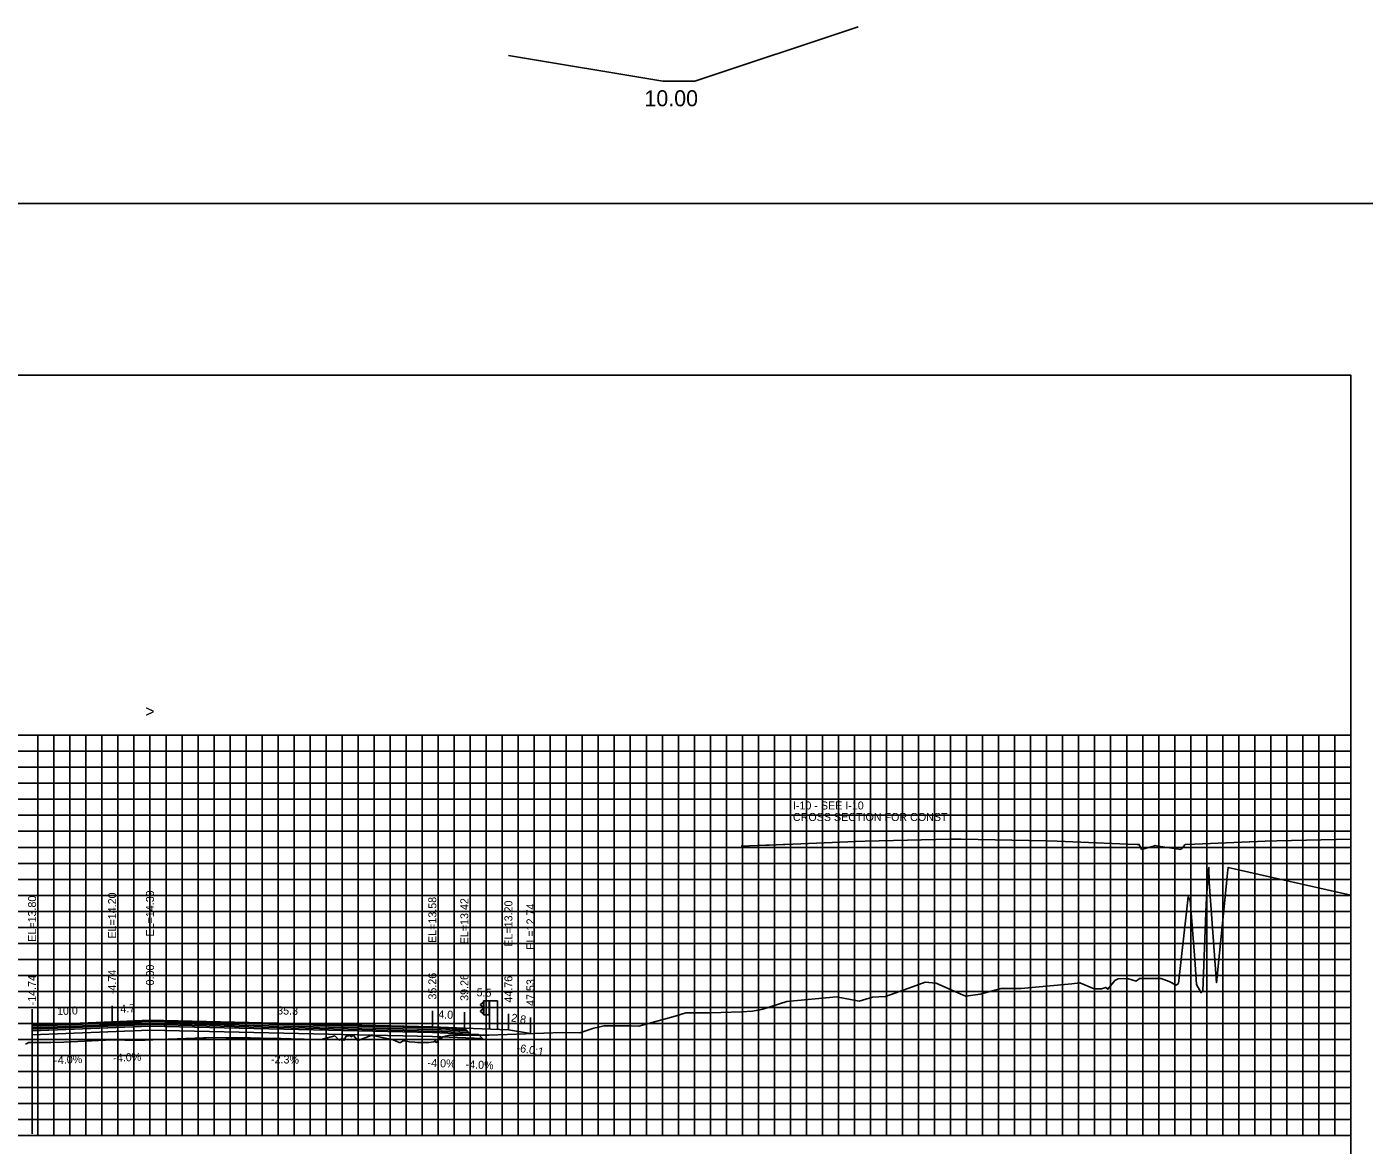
# Model space of a CAD drawing. Extents: x 1797518 to 1804843, y 248068 to 251132.
# Drawn here: x 1804315.6 to 1804482.7, y 250173.2 to 250312.9 of the extents above; entities that cross this region are included whole.
import ezdxf

# ---------------------------------------------------------------- set-up
doc = ezdxf.new("R2010")
doc.units = 0
for name, color, linetype in [('1', 7, 'Continuous'), ('3', 7, 'Continuous'), ('4', 7, 'Continuous'), ('60', 7, 'Continuous'), ('BASE', 7, 'Continuous'), ('CL-CNST', 7, 'Continuous'), ('Level 1', 7, 'Continuous'), ('Level 62', 7, 'Continuous'), ('LOWER BINDER', 7, 'Continuous'), ('M-ROADS', 7, 'Continuous'), ('UPPER BINDER', 7, 'Continuous'), ('WEARING', 7, 'Continuous')]:
    doc.layers.add(name, color=color, linetype=linetype)

msp = doc.modelspace()

# ---------------------------------------------------------------- linework, layer by layer
for p, q in [((1804326.27, 250188.63), (1804326.27, 250190.63)), ((1804331, 250188.82), (1804331, 250190.82)), ((1804316.27, 250188.23), (1804316.27, 250190.23)), ((1804366.27, 250188.01), (1804366.27, 250190.01)), ((1804370.27, 250187.85), (1804370.27, 250189.85)), ((1804375.77, 250187.63), (1804375.77, 250189.63)), ((1804378.53, 250187.17), (1804378.53, 250189.17))]:
    msp.add_line(p, q)
msp.add_lwpolyline([(1804181, 250079.43), (1804481, 250079.43), (1804481, 250269.43), (1804181, 250269.43)], close=True)
at = {"layer": '1'}
for p, q in [((1804419.48, 250312.95), (1804399.05, 250306.14)), ((1804375.77, 250309.35), (1804395.05, 250306.14)), ((1804399.05, 250306.14), (1804395.05, 250306.14))]:
    msp.add_line(p, q, dxfattribs=at)
msp.add_lwpolyline([(1804164.33, 250290.86), (1804501.93, 250290.86), (1804501.93, 250044.24), (1804164.33, 250044.24)], close=True, dxfattribs=at)
at = {"layer": '3'}
msp.add_line((1804316.27, 250188.41), (1804316.27, 250174.63), dxfattribs=at)
at = {"layer": '60'}
for p, q in [((1804481, 250174.43), (1804481, 250224.43)), ((1804481.06, 250224.43), (1804481, 250224.43)), ((1804481.06, 250214.43), (1804481, 250214.43)), ((1804481.06, 250204.43), (1804481, 250204.43)), ((1804481.06, 250194.43), (1804481, 250194.43)), ((1804481.06, 250184.43), (1804481, 250184.43)), ((1804181, 250174.43), (1804481, 250174.43)), ((1804321, 250174.37), (1804321, 250174.43)), ((1804331, 250174.37), (1804331, 250174.43)), ((1804341, 250174.37), (1804341, 250174.43)), ((1804351, 250174.37), (1804351, 250174.43)), ((1804361, 250174.37), (1804361, 250174.43)), ((1804371, 250174.37), (1804371, 250174.43)), ((1804381, 250174.37), (1804381, 250174.43)), ((1804391, 250174.37), (1804391, 250174.43)), ((1804401, 250174.37), (1804401, 250174.43)), ((1804411, 250174.37), (1804411, 250174.43)), ((1804421, 250174.37), (1804421, 250174.43)), ((1804431, 250174.37), (1804431, 250174.43)), ((1804441, 250174.37), (1804441, 250174.43)), ((1804451, 250174.37), (1804451, 250174.43)), ((1804461, 250174.37), (1804461, 250174.43)), ((1804471, 250174.37), (1804471, 250174.43)), ((1804481, 250174.37), (1804481, 250174.43)), ((1804481.06, 250174.43), (1804481, 250174.43))]:
    msp.add_line(p, q, dxfattribs=at)
at = {"layer": 'BASE'}
msp.add_lwpolyline([(1804316.27, 250187.51), (1804331, 250188.1), (1804366.27, 250187.29), (1804371.02, 250187.1), (1804372.02, 250187.06), (1804372.54, 250186.54), (1804366.27, 250186.79), (1804331, 250187.6), (1804316.27, 250187.01)], close=True, dxfattribs=at)
at = {"layer": 'CL-CNST'}
for points in [[(1804404.83, 250210.58), (1804407.91, 250210.7), (1804408.33, 250210.72), (1804410.09, 250210.79), (1804410.33, 250210.8), (1804419.13, 250211.15), (1804420.33, 250211.2), (1804430.9, 250211.43), (1804432.33, 250211.46), (1804442.9, 250211.23), (1804444.33, 250211.2), (1804453.14, 250210.84), (1804454.33, 250210.8), (1804454.55, 250210.79), (1804454.58, 250210.79), (1804454.83, 250210.26), (1804454.87, 250210.18), (1804456.37, 250210.59), (1804456.58, 250210.65), (1804456.92, 250210.59), (1804459.78, 250210.18), (1804459.84, 250210.26), (1804460.32, 250210.8), (1804461.51, 250210.84), (1804470.32, 250211.2), (1804471.74, 250211.23), (1804481, 250211.43)], [(1804316.27, 250188.23), (1804326.27, 250188.63), (1804331, 250188.82), (1804366.27, 250188.01), (1804370.27, 250187.85), (1804375.77, 250187.63), (1804378.53, 250187.17)]]:
    msp.add_lwpolyline(points, dxfattribs=at)
at = {"layer": 'Level 1'}
for p, q in [((1804372.65, 250191.1), (1804372.28, 250190.8)), ((1804372.28, 250190.73), (1804372.65, 250190.45)), ((1804372.65, 250190.31), (1804372.28, 250190.01)), ((1804372.65, 250191.25), (1804372.65, 250189.5)), ((1804374.4, 250191.25), (1804372.65, 250191.25)), ((1804372.7, 250191.25), (1804372.7, 250189.5)), ((1804373.35, 250191.25), (1804373.35, 250189.5)), ((1804373.4, 250191.25), (1804373.4, 250187.73)), ((1804374.4, 250191.25), (1804374.4, 250187.69)), ((1804372.28, 250189.94), (1804372.65, 250189.65)), ((1804373.4, 250189.5), (1804372.65, 250189.5))]:
    msp.add_line(p, q, dxfattribs=at)
for centre in [(1804372.32, 250190.77), (1804372.32, 250189.97)]:
    msp.add_arc(centre, 0.05, 135, 226.6208, dxfattribs=at)
at = {"layer": 'Level 62'}
for p, q in [((1804181, 250224.43), (1804481, 250224.43)), ((1804317, 250174.43), (1804317, 250224.43)), ((1804319, 250174.43), (1804319, 250224.43)), ((1804321, 250174.43), (1804321, 250224.43)), ((1804323, 250174.43), (1804323, 250224.43)), ((1804325, 250174.43), (1804325, 250224.43)), ((1804327, 250174.43), (1804327, 250224.43)), ((1804329, 250174.43), (1804329, 250224.43)), ((1804331, 250174.43), (1804331, 250224.43)), ((1804333, 250174.43), (1804333, 250224.43)), ((1804335, 250174.43), (1804335, 250224.43)), ((1804337, 250174.43), (1804337, 250224.43)), ((1804339, 250174.43), (1804339, 250224.43)), ((1804341, 250174.43), (1804341, 250224.43)), ((1804343, 250174.43), (1804343, 250224.43)), ((1804345, 250174.43), (1804345, 250224.43)), ((1804347, 250174.43), (1804347, 250224.43)), ((1804349, 250174.43), (1804349, 250224.43)), ((1804351, 250174.43), (1804351, 250224.43)), ((1804353, 250174.43), (1804353, 250224.43)), ((1804355, 250174.43), (1804355, 250224.43)), ((1804357, 250174.43), (1804357, 250224.43)), ((1804359, 250174.43), (1804359, 250224.43)), ((1804361, 250174.43), (1804361, 250224.43)), ((1804363, 250174.43), (1804363, 250224.43)), ((1804365, 250174.43), (1804365, 250224.43)), ((1804367, 250174.43), (1804367, 250224.43)), ((1804369, 250174.43), (1804369, 250224.43)), ((1804371, 250174.43), (1804371, 250224.43)), ((1804373, 250174.43), (1804373, 250224.43)), ((1804375, 250174.43), (1804375, 250224.43)), ((1804377, 250174.43), (1804377, 250224.43)), ((1804379, 250174.43), (1804379, 250224.43)), ((1804381, 250174.43), (1804381, 250224.43)), ((1804383, 250174.43), (1804383, 250224.43)), ((1804385, 250174.43), (1804385, 250224.43)), ((1804387, 250174.43), (1804387, 250224.43)), ((1804389, 250174.43), (1804389, 250224.43)), ((1804391, 250174.43), (1804391, 250224.43)), ((1804393, 250174.43), (1804393, 250224.43)), ((1804395, 250174.43), (1804395, 250224.43)), ((1804397, 250174.43), (1804397, 250224.43)), ((1804399, 250174.43), (1804399, 250224.43)), ((1804401, 250174.43), (1804401, 250224.43)), ((1804403, 250174.43), (1804403, 250224.43)), ((1804405, 250174.43), (1804405, 250224.43)), ((1804407, 250174.43), (1804407, 250224.43)), ((1804409, 250174.43), (1804409, 250224.43)), ((1804411, 250174.43), (1804411, 250224.43)), ((1804413, 250174.43), (1804413, 250224.43)), ((1804415, 250174.43), (1804415, 250224.43)), ((1804417, 250174.43), (1804417, 250224.43)), ((1804419, 250174.43), (1804419, 250224.43)), ((1804421, 250174.43), (1804421, 250224.43)), ((1804423, 250174.43), (1804423, 250224.43)), ((1804425, 250174.43), (1804425, 250224.43)), ((1804427, 250174.43), (1804427, 250224.43)), ((1804429, 250174.43), (1804429, 250224.43)), ((1804431, 250174.43), (1804431, 250224.43)), ((1804433, 250174.43), (1804433, 250224.43)), ((1804435, 250174.43), (1804435, 250224.43)), ((1804437, 250174.43), (1804437, 250224.43)), ((1804439, 250174.43), (1804439, 250224.43)), ((1804441, 250174.43), (1804441, 250224.43)), ((1804443, 250174.43), (1804443, 250224.43)), ((1804445, 250174.43), (1804445, 250224.43)), ((1804447, 250174.43), (1804447, 250224.43)), ((1804449, 250174.43), (1804449, 250224.43)), ((1804451, 250174.43), (1804451, 250224.43)), ((1804453, 250174.43), (1804453, 250224.43)), ((1804455, 250174.43), (1804455, 250224.43)), ((1804457, 250174.43), (1804457, 250224.43)), ((1804459, 250174.43), (1804459, 250224.43)), ((1804461, 250174.43), (1804461, 250224.43)), ((1804463, 250174.43), (1804463, 250224.43)), ((1804465, 250174.43), (1804465, 250224.43)), ((1804467, 250174.43), (1804467, 250224.43)), ((1804469, 250174.43), (1804469, 250224.43)), ((1804471, 250174.43), (1804471, 250224.43)), ((1804473, 250174.43), (1804473, 250224.43)), ((1804475, 250174.43), (1804475, 250224.43)), ((1804477, 250174.43), (1804477, 250224.43)), ((1804479, 250174.43), (1804479, 250224.43)), ((1804481, 250174.43), (1804481, 250224.43)), ((1804181, 250222.43), (1804481, 250222.43)), ((1804181, 250220.43), (1804481, 250220.43)), ((1804181, 250218.43), (1804481, 250218.43)), ((1804181, 250216.43), (1804481, 250216.43)), ((1804181, 250214.43), (1804481, 250214.43)), ((1804181, 250212.43), (1804481, 250212.43)), ((1804181, 250210.43), (1804481, 250210.43)), ((1804181, 250208.43), (1804481, 250208.43)), ((1804181, 250206.43), (1804481, 250206.43)), ((1804181, 250204.43), (1804481, 250204.43)), ((1804181, 250202.43), (1804481, 250202.43)), ((1804181, 250200.43), (1804481, 250200.43)), ((1804181, 250198.43), (1804481, 250198.43)), ((1804181, 250196.43), (1804481, 250196.43)), ((1804181, 250194.43), (1804481, 250194.43)), ((1804181, 250192.43), (1804481, 250192.43)), ((1804181, 250190.43), (1804481, 250190.43)), ((1804181, 250188.43), (1804481, 250188.43)), ((1804181, 250186.43), (1804481, 250186.43)), ((1804181, 250184.43), (1804481, 250184.43)), ((1804181, 250182.43), (1804481, 250182.43)), ((1804181, 250180.43), (1804481, 250180.43)), ((1804181, 250178.43), (1804481, 250178.43)), ((1804181, 250176.43), (1804481, 250176.43)), ((1804181, 250174.43), (1804481, 250174.43))]:
    msp.add_line(p, q, dxfattribs=at)
at = {"layer": 'LOWER BINDER'}
for points in [[(1804331, 250188.48), (1804366.27, 250187.67), (1804370.62, 250187.49), (1804370.82, 250187.3), (1804366.27, 250187.48), (1804331, 250188.29), (1804316.27, 250187.7), (1804316.27, 250187.89)], [(1804331, 250188.29), (1804366.27, 250187.48), (1804370.82, 250187.3), (1804371.02, 250187.1), (1804366.27, 250187.29), (1804331, 250188.1), (1804316.27, 250187.51), (1804316.27, 250187.7)]]:
    msp.add_lwpolyline(points, close=True, dxfattribs=at)
at = {"layer": 'M-ROADS'}
msp.add_lwpolyline([(1804315.46, 250185.85), (1804315.67, 250185.92), (1804315.81, 250186.06), (1804316.01, 250186.04), (1804316.21, 250186.03), (1804316.48, 250186.06), (1804318.27, 250186.03), (1804318.63, 250186.03), (1804320.25, 250186.1), (1804325.45, 250186.36), (1804326.59, 250186.37), (1804327.84, 250186.36), (1804327.95, 250186.35), (1804328.69, 250186.35), (1804329.79, 250186.36), (1804330.39, 250186.36), (1804333.29, 250186.47), (1804337.67, 250186.63), (1804338.02, 250186.64), (1804339.01, 250186.66), (1804340.47, 250186.65), (1804340.51, 250186.65), (1804340.81, 250186.65), (1804342.21, 250186.63), (1804342.97, 250186.65), (1804343.54, 250186.64), (1804344.79, 250186.61), (1804347.37, 250186.55), (1804349.92, 250186.46), (1804350.26, 250186.46), (1804352.03, 250186.38), (1804352.31, 250186.42), (1804352.54, 250186.46), (1804354.07, 250186.86), (1804354.1, 250186.87), (1804354.1, 250186.86), (1804354.64, 250186.35), (1804354.87, 250186.46), (1804354.87, 250186.44), (1804354.91, 250186.57), (1804354.95, 250186.27), (1804354.96, 250186.28), (1804354.97, 250186.29), (1804354.97, 250186.33), (1804354.98, 250186.43), (1804354.99, 250186.63), (1804355.22, 250186.38), (1804355.22, 250186.32), (1804355.23, 250186.31), (1804355.26, 250186.37), (1804355.5, 250186.84), (1804355.67, 250186.83), (1804355.68, 250186.88), (1804355.85, 250186.88), (1804356, 250186.95), (1804356.14, 250186.77), (1804356.33, 250186.94), (1804356.4, 250186.93), (1804356.95, 250186.31), (1804357.02, 250186.3), (1804357.09, 250186.33), (1804358.62, 250186.93), (1804358.85, 250186.94), (1804361.38, 250186.38), (1804362.14, 250186.06), (1804362.32, 250186.06), (1804362.32, 250186.06), (1804362.36, 250186.07), (1804362.68, 250186.31), (1804362.74, 250186.24), (1804363.4, 250186.12), (1804364.07, 250186.07), (1804364.42, 250186.06), (1804365.02, 250186.05), (1804365.24, 250186.05), (1804365.84, 250186.06), (1804366.47, 250186.14), (1804366.58, 250186.18), (1804366.61, 250186.31), (1804366.64, 250186.21), (1804366.75, 250186.04), (1804366.89, 250186.07), (1804367.14, 250186.8), (1804367.32, 250186.42), (1804367.54, 250186.75), (1804368.43, 250186.97), (1804369.99, 250186.97), (1804372.08, 250186.97), (1804372.83, 250186.97), (1804373.33, 250186.98), (1804382.49, 250187.31), (1804384.69, 250187.25), (1804386.46, 250187.82), (1804387.72, 250188.15), (1804389.17, 250188.15), (1804391.11, 250188.15), (1804392.05, 250188.1), (1804396.62, 250189.32), (1804397.93, 250189.76), (1804399.22, 250189.76), (1804400.93, 250189.76), (1804402.36, 250189.81), (1804404.89, 250189.89), (1804406.25, 250189.96), (1804407.4, 250190.18), (1804407.56, 250190.23), (1804410.57, 250191.19), (1804416.76, 250191.74), (1804419.57, 250191.23), (1804421.25, 250191.71), (1804422.89, 250191.8), (1804426.26, 250193.01), (1804427.84, 250193.57), (1804429.22, 250193.44), (1804432.29, 250192.09), (1804432.92, 250191.82), (1804434.69, 250192.07), (1804437.32, 250192.81), (1804437.77, 250192.81), (1804438.1, 250192.81), (1804439.81, 250192.8), (1804446.15, 250193.36), (1804447.16, 250193.51), (1804448.96, 250192.74), (1804449.86, 250192.74), (1804450.39, 250192.93), (1804450.66, 250192.7), (1804451.53, 250193.78), (1804451.93, 250194.01), (1804453.1, 250194.03), (1804454.19, 250193.71), (1804454.59, 250194.05), (1804454.72, 250194.05), (1804454.93, 250194.05), (1804456.76, 250194.04), (1804456.86, 250194.05), (1804457.3, 250194.03), (1804458.29, 250193.65), (1804459.18, 250193.22), (1804459.46, 250193.43), (1804460.68, 250204.24), (1804460.93, 250203.82), (1804461.5, 250196.41), (1804461.72, 250193.28), (1804462.3, 250192.26), (1804462.53, 250192.45), (1804462.95, 250203.36), (1804463.16, 250207.28), (1804463.27, 250207.93), (1804463.32, 250206.07), (1804464.21, 250193.52), (1804465.38, 250205.06), (1804465.6, 250207.25), (1804465.67, 250207.93), (1804472.12, 250206.46), (1804481, 250204.44)], dxfattribs=at)
at = {"layer": 'UPPER BINDER'}
msp.add_lwpolyline([(1804370.62, 250187.49), (1804370.42, 250187.69), (1804366.27, 250187.86), (1804331, 250188.67), (1804316.27, 250188.08), (1804316.27, 250187.89), (1804331, 250188.48), (1804366.27, 250187.67)], close=True, dxfattribs=at)
at = {"layer": 'WEARING'}
msp.add_lwpolyline([(1804370.42, 250187.69), (1804370.27, 250187.85), (1804366.27, 250188.01), (1804331, 250188.82), (1804326.27, 250188.63), (1804316.27, 250188.23), (1804316.27, 250188.08), (1804331, 250188.67), (1804366.27, 250187.86)], close=True, dxfattribs=at)

# ---------------------------------------------------------------- texts
msp.add_text('-6.0:1', height=1, rotation=350.5377).set_placement((1804376.74, 250184.93))
at = {"layer": '1'}
msp.add_text('10.00', height=2, dxfattribs=at).set_placement((1804392.76, 250303.01))
at = {"layer": '3'}
for s, p in [('I-10 - SEE I-10', (1804411.31, 250215.16)), ('CROSS SECTION FOR CONST ', (1804411.31, 250213.72))]:
    msp.add_text(s, height=1, dxfattribs=at).set_placement(p)
for s, p in [('EL=13.80', (1804316.77, 250198.63)), ('EL=14.20', (1804326.77, 250199.03)), ('EL=14.39', (1804331.5, 250199.29)), ('EL=13.58', (1804366.77, 250198.48)), ('EL=13.42', (1804370.77, 250198.32)), ('EL=13.20', (1804376.27, 250198.02)), ('EL=12.74', (1804379.03, 250197.64)), ('0.00', (1804331.5, 250193.18)), ('-14.74', (1804316.77, 250190.69)), ('-4.74', (1804326.77, 250192.08)), ('35.26', (1804366.77, 250191.41)), ('39.26', (1804370.77, 250191.25)), ('44.76', (1804376.27, 250191.03)), ('47.53', (1804379.03, 250190.62))]:
    msp.add_text(s, height=1, rotation=90, dxfattribs=at).set_placement(p)
at = {"layer": '4'}
for s, rotation, p in [('5.5', 357.7094, (1804371.78, 250191.83)), ('10.0', 2.2906, (1804319.4, 250189.46)), ('4.7', 2.2906, (1804327.31, 250189.77)), ('35.3', 358.6778, (1804346.88, 250189.56)), ('4.0', 357.7094, (1804366.99, 250189.08)), ('2.8', 350.5377, (1804376.06, 250188.69)), ('-4.0%', 2.2906, (1804319.06, 250183.34)), ('-4.0%', 2.2906, (1804326.43, 250183.63)), ('-2.3%', 358.6778, (1804346.11, 250183.47)), ('-4.0%', 357.7094, (1804365.66, 250183.03)), ('-4.0%', 357.7094, (1804370.41, 250182.84))]:
    msp.add_text(s, height=1, rotation=rotation, dxfattribs=at).set_placement(p)
at = {"layer": '60'}
msp.add_text('>', height=1.5, dxfattribs=at).set_placement((1804330.39, 250226.68))

doc.saveas('drawing.dxf')
